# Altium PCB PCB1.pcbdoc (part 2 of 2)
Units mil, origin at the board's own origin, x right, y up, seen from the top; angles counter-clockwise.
Board outline 4100 x 4075 mil, 2 copper layers (Top Layer, Bottom Layer); 99 components, 67 nets, 330 pads, 1473 vias.
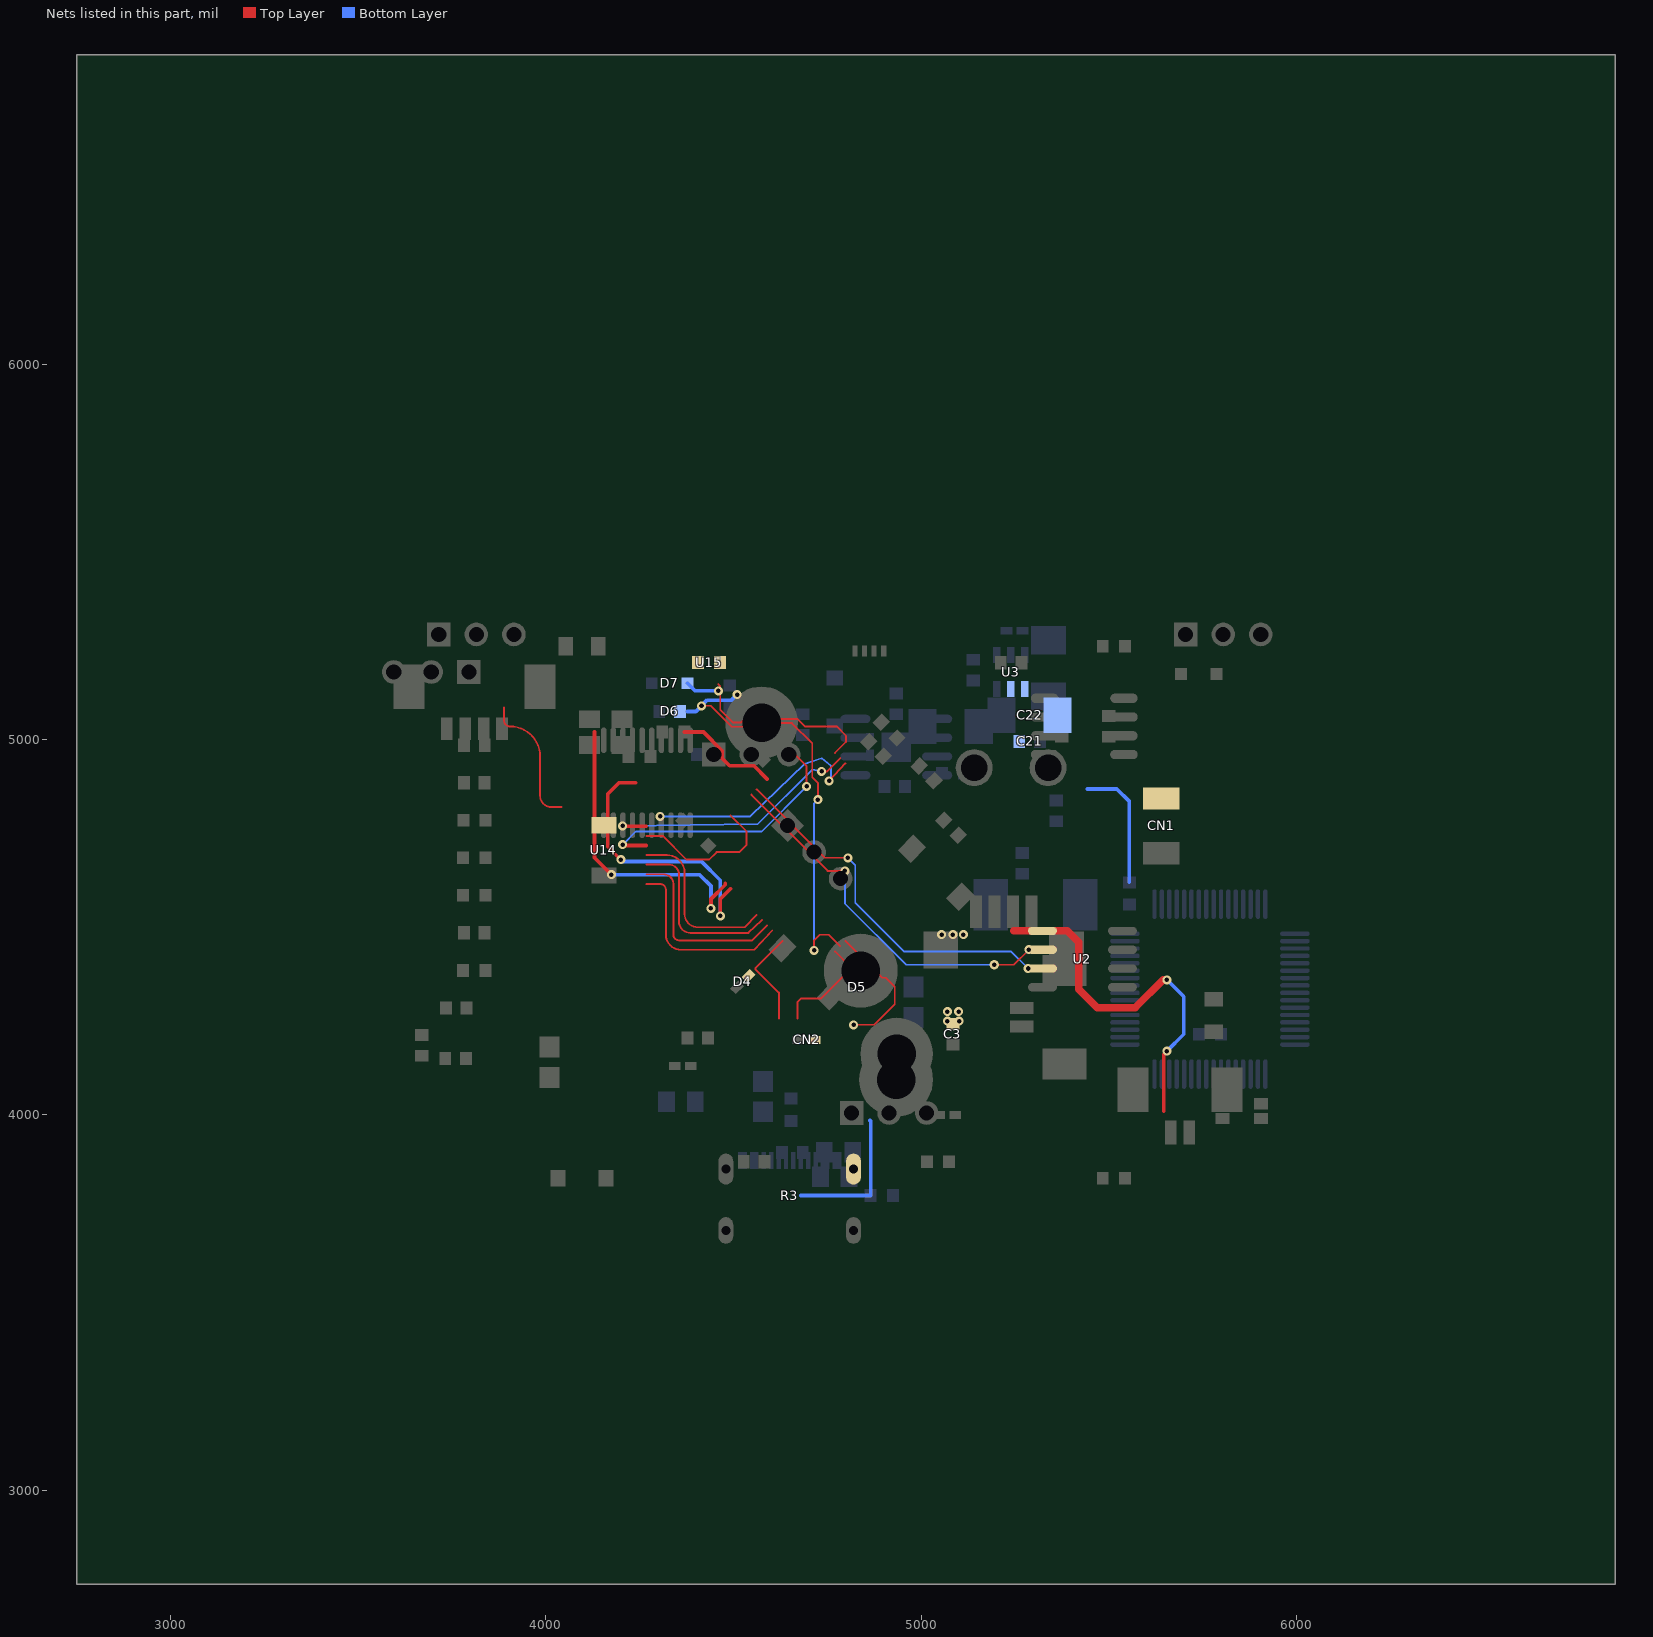
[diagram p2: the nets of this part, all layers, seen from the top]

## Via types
v1: diameter 24, hole 12, Top Layer to Bottom Layer, 1389 vias
v2: diameter 24.02, hole 12.01, Top Layer to Bottom Layer, 83 vias
v3: diameter 20.08, hole 12.01, Top Layer to Bottom Layer, 1 vias

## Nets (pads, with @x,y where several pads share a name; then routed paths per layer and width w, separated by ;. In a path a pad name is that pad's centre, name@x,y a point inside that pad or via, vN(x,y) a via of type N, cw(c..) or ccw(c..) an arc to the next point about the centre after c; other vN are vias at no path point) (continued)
SER.8:  | length 363.9
  Top Layer w5: 3888.74,5085 3888.74,5051.26 ccw(c3905,5051.26) 3905,5035 cw(c3905,4955) 3985,4955 3985,4850 ccw(c4014.84,4850) 4014.84,4820.16 4041.97,4820.16
SERVO_EN:  | length 361
  Top Layer w5: 4798.51,4463.37 4896.37,4365.51 4905.51,4365.51 4930,4341.02 4930,4295 4875,4240 v2(4820,4240)
SWD_CLK: CN2.2 D5.1 | length 284.6
  Top Layer w5: 4670.4,4256.1 4670.4,4300.4 4680,4310 4732.97,4310 4796.48,4373.52 4810,4387.03 4810,4396.21 4770.67,4435.53
SWD_IO: D4.1 | length 263.5
  Top Layer w5: 4621.2,4256.1 4621.2,4325.83 4558.52,4388.52 4558.52,4390.4 4631.49,4463.37
TIM1_CH1:  | length 464.8
  Top Layer w5: 4268.03,4692.21 4322.79,4692.21 cw(c4322.79,4645) 4370,4645 4370,4535 ccw(c4405,4535) 4405,4500 4530,4500 4561.89,4532.97
TIM1_CH2:  | length 478.7
  Top Layer w5: 4268.03,4666.61 4328.39,4666.61 cw(c4328.39,4640) 4355,4640 4355,4515 ccw(c4385,4515) 4385,4485 4540,4485 4575.81,4519.05
TIM1_CH3:  | length 496.8
  Top Layer w5: 4268.03,4641.02 4314.21,4641.02 cw(c4314.21,4615.23) 4340,4615.23 4340,4480 ccw(c4355,4480) 4355,4465 4549.59,4465 4589.73,4505.14
TIM1_CH4: U14.2 | length 509.2
  Top Layer w5: 4268.03,4615.43 ccw(c4268.46,4615.43) 4268.46,4615 4305,4615 cw(c4305,4600) 4320,4600 4320,4480 ccw(c4360,4480) 4360,4440 4555,4440 4603.65,4491.21
TIM2_CH1:  | length 624.8
  Top Layer w5: v2(4755,4890) 4798.51,4936.63
  Bottom Layer w5: v2(4305,4795) 4545,4795 4690,4935 4735,4950 4760,4930 v2@4760,4890
TIM2_CH2:  | length 718.2
  Top Layer w5: v2(4735,4915) 4750,4915 4784.59,4950.54
  Top Layer w10: v2(4205,4770) 4268.03,4768.98
  Bottom Layer w5: v2(4205,4770) 4565,4775 4710,4920 v2(4735,4915)
TIM2_CH3:  | length 405.1
  Top Layer w5: 4268.03,4743.39 4311.61,4743.39 4375,4680 4435,4680 4455,4700 4515,4700 4535,4720 4535,4755 4492.57,4797.43 4492.3,4797.43
TIM2_CH4:  | length 722.7
  Top Layer w5: 4659.33,4964.47 4695,4928.79 v2(4695,4875)
  Top Layer w10: v2(4205,4720) ccw(c4207.2,4720) 4207.2,4717.8 4268.03,4717.8
  Bottom Layer w5: v2(4205,4720) 4240,4755 4575,4755 v2(4695,4875)
TIM15_CH1:  | length 818.5
  Top Layer w10: 4130,5020 4130,4685 v2(4175,4640) ; v2(4440,4550) 4440,4575 4478.37,4613.37 4478.37,4616.49
  Bottom Layer w10: v2(4175,4640) 4410,4640 4440,4610 v2(4440,4550)
TIM15_CH2:  | length 743.6
  Top Layer w10: v2(4200,4680) 4165,4715 4165,4855 4195,4885 4240,4885 ; v2(4465,4530) 4465,4575.27 4492.3,4602.57
  Bottom Layer w10: v2(4200,4680) 4205,4675 4415,4675 4465,4625 v2(4465,4530)
TIM16_CH1:  | length 283.6
  Top Layer w10: 4369.66,5020 4420,5020 4470,4970 4470,4950 4490,4930 4554.59,4930 4589.73,4894.86
UART2_RX: D6.1 U15.1 | length 1173.3
  Top Layer w5: v2(4415,5090) 4439.44,5090 4495.44,5034 4524.56,5034 4534.56,5044 4656,5044 4710,4990 4710,4900 4725,4885 v2(4725,4840) ; v2(4715,4438.25) 4715,4465 4730,4480 4754.05,4480 4784.59,4449.46
  Bottom Layer w5: v2(4715,4438.25) 4715,4830 v2(4725,4840)
  Bottom Layer w10: 4377.4,5075 4400,5075 v2(4415,5090) 4430,5105 4495,5105 v2(4510,5120)
UART2_TX: D7.1 U15.2 | length 591
  Top Layer w5: 4459.6,5147.91 4465,5142.52 4465,5080 4500,5045 4520,5045 4530,5055 4670,5055 4690,5035 4775,5035 4800,5010 4800,4993.79 4770.67,4964.47
  Bottom Layer w10: D7.1@4377.4,5150 4397.4,5130 v2(4460,5130)
UART3_RX: U2.6 | length 992.7
  Top Layer w5: 4547.97,4853.11 4751.08,4650 v2@4795,4650 ; v2(5195,4400) 5247.55,4400 v2(5287.55,4440)
  Bottom Layer w5: v2(4797.31,4650) 4797.31,4562.69 4960,4400 v2(5195,4400)
UART3_TX: U2.7 | length 979.3
  Top Layer w5: 4561.89,4867.03 4743.92,4685 v2(4805,4685)
  Bottom Layer w5: v2(4805,4685) 4824.51,4665.49 4824.51,4565.49 4955,4435 5240,4435 v2(5285,4390)
USB_5V: U2.5 | length 987.4
  Top Layer w10: 5646.69,4010 5646.69,4161.69 v2(5655,4170)
  Top Layer w20: 5247.56,4490 5324.39,4490 5390,4490 5420,4460 5420,4335 5470,4285 5570,4285 5645,4360 v2(5655,4360)
  Bottom Layer w10: v2(5655,4170) 5700,4215 5700,4315 v2(5655,4360)
VCC: C3.1 C21.1 C22.1 CN1.2 U3.4 U3.5 | length 341
  Bottom Layer w10: 5443.15,4868.43 5521.57,4868.43 5555,4835 5555,4619.66
  other v2: 5070,4250 5101.64,4250 5070,4275 5100,4275 5055,4480 5085,4480 5112.44,4480
VREF1: R3.1 | length 386.9
  Bottom Layer w10: 4679.66,3785 4865.68,3785 4865.68,3982.72 ccw(c4863.7,3982.72) 4863.7,3984.7
"": 
pads on no net: C1.2 C2.2 C3.2 C4.2 C7.2 C8.2 C9.2 C10.2 C11.2 C12.2 C12.3 C12.4 C12.5 C12.6 C13.2 C13.3 C13.4 C13.5 C13.6 C13.7 C13.8 C13.9 C14.2 C14.3 C14.4 C15.2 C16.2 C18.1 C19.1 C20.2 C21.2 C22.2 C23.2 C24.2 C24.3 C25.2 C26.2 C27.2 C28.2 C28.3 C29.2 C79.2 CN1.1 CN2.1 D1.1 D2.2 D3.1 D4.2 D5.2 D6.2 D7.2 D8.2 D8.3 D9.2 D10.2 D11.2 H1.1 H1.2 H2.1 H2.2 H3.1 H3.2 H4.1 H4.2 L1.1 L2.2 LED1.2 LED2.2 LED2.3 LED2.4 LED3.1 R1.2 R2.2 R3.2 R3.3 R3.4 R3.A1B12 R3.A4B9 R3.A5 R3.A6 R3.A7 R3.A8 R3.B1A12 R3.B4A9 R3.B5 R3.B6 R3.B7 R3.B8 R4.2 R5.2 R6.2 R6.3 R6.4 R7.2 R8.2 R8.3 R8.4 R8.5 R8.6 R8.7 R8.8 R8.9 R8.10 R8.11 R8.12 R8.13 R8.14 R8.15 R8.16 R8.17 R8.18 R8.19 R8.20 R8.21 R8.22 R8.23 R8.24 R8.25 R8.26 R8.27 R8.28 R8.29 R8.30 R8.31 R8.32 R8.33 R8.34 R8.35 R8.36 R8.37 R8.38 R8.39 R8.40 R8.41 R8.42 R8.43 R8.44 R8.45 R8.46 R8.47 R8.48 R8.49 R8.50 R8.51 R8.52 R8.53 R8.54 R8.55 R8.56 R8.57 R8.58 R8.59 R8.60 R8.61 R8.62 R8.63 R8.64 R9.2 R10.2 R13.2 R13.3 R13.4 R13.5 R13.6 R13.7 R13.8 R14.2 R15.2 R15.3 R15.4 R15.5 R15.6 R15.7 R15.8 R15.9 R15.10 R15.11 R15.12 R15.13 R15.14 R15.15 R15.16 R15.17 R15.18 R15.19 R15.20 R16.2 R16.3 R16.4 R17.2 SW1.2 SW1.3 SW2.2 SW2.3 U2.1 U2.4 U3.6 U4.5 U5.2 U5.3 U6.2 U7.2 U8.2 U9.2 U10.2 U11.1 U12.1 U13.1 U14.1 U18.1 U19.1 U20.1 U21.1 U22.1 U23.1 U24.1 U25.1 U25.4 U25.5 U25.6 X1.1
copper on no net:
  other v1: 4914.33,4960.17 4953.73,4960.17 4914.33,4999.57 4953.73,4999.57

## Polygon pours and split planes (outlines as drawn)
GND on Top Layer (solid, remove dead copper): 3150,3350 6520,3350 6520,6155 3150,6155
GND on Bottom Layer (solid, remove dead copper, pour order 1): 3000,3000 6600,3000 6600,6575 3000,6575

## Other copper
Top Layer:
  region net VCC: 5045,4370 5125,4370 5125,4490 5045,4490
  region net SER.5V: 3775,3965 4210,3965 4210,4105 3775,4105
  region net SER.5V: 3776.02,4070 3845,4070 3845,5124.37 3776.02,5124.37
  pour cut-out net CAN_TX: 5162.5,4772.89 5167.5,4772.89 5173.75,4784.33 5156.25,4784.33
  pour cut-out net 5V: 5243.78,4859.85 5253.81,4845.7 5276.19,4845.7 5250.85,4866.92
  pour cut-out net CAN_RX: 5307.5,4775.5 5312.5,4775 5318.75,4780.76 5303.81,4791.3
  pour cut-out net CAN_H: 5217.5,4985.89 5223.75,4997.33 5206.25,4997.33 5212.5,4985.89
  pour cut-out net CAN_H: 5210.39,5083.9 5203.81,5058.7 5226.19,5058.7 5220.39,5083.5
  pour cut-out net CAN_L: 5267.5,4985.89 5273.75,4997.33 5256.25,4997.33 5262.5,4985.89
  pour cut-out net CAN_L: 5260,5083.71 5253.81,5058.7 5276.19,5058.7 5270,5083.71
  pour cut-out net $1N15560: 5321.46,5068.54 5303.81,5058.7 5326.19,5058.7 5328.54,5061.46
  pour cut-out net 5V: 4356.18,5191.18 4345.43,5179.41 4376.93,5179.41 4366.18,5191.18
  pour cut-out net UART2_TX: 4462.5,5108.92 4467.5,5108.92 4473.75,5116.42 4456.25,5116.42
  pour cut-out net 5V: 5113.82,3893.82 5123.82,3893.82 5134.57,3900.59 5103.07,3900.59
  pour cut-out net 5V: 5142.09,3941.93 5134.57,3963.58 5134.57,3900.59 5142.09,3922.24
  pour cut-out net I2C1_SCL: 5022.5,3971.08 5017.5,3971.08 5011.25,3963.58 5028.75,3963.58
  pour cut-out net I2C1_SDA: 4968.68,3971.08 4962.43,3963.58 4979.93,3963.58 4973.68,3971.08
  pour cut-out net 5V: 4659.57,3937.09 4644.57,3949.59 4644.57,3914.59 4659.57,3927.09
  pour cut-out net I2C2_SCL: 4525.4,3978.58 4514.65,3963.58 4546.14,3963.58 4535.4,3978.58
  pour cut-out net I2C2_SDA: 4476.18,3978.58 4465.43,3963.58 4496.93,3963.58 4486.18,3978.58
  pour cut-out net CAN_L: 4917.46,5152.91 4902.46,5165.41 4902.46,5130.41 4917.46,5142.91
  pour cut-out net CAN_H: 4832.5,5112.5 4842.5,5112.5 4853.25,5116.42 4821.75,5116.42
  pour cut-out net CAN_L: 5269.6,5194.41 5259.6,5194.41 5248.85,5179.41 5280.35,5179.41
  pour cut-out net CAN_L: 5260,5101.42 5270,5101.42 5280.35,5116.42 5248.85,5116.42
  pour cut-out net CAN_H: 5210.39,5101.42 5220.39,5101.42 5231.14,5116.42 5199.65,5116.42
  pour cut-out net CAN_H: 5196.01,5121.46 5208.65,5116.42 5199.65,5156.92 5189.04,5128.63
  pour cut-out net $1N20010: 4296.18,4905.55 4306.18,4905.55 4318.68,4920.55 4283.68,4920.55
  pour cut-out net 3V3: 4230.31,4940.31 4217.52,4950.08 4217.52,4920.55 4230.31,4930.31
  pour cut-out net $1N20360: 4296.18,5004.45 4283.68,4989.45 4318.68,4989.45 4306.18,5004.45
  pour cut-out net $1N20185: 4203.82,5004.45 4193.82,5004.45 4181.32,4989.45 4216.32,4989.45
  pour cut-out net 5V: 4220.77,4594.84 4220.77,4584.84 4240.9,4582.67 4240.9,4597.01
  pour cut-out net 5V: 4306.5,4594.84 4295.16,4597.01 4295.16,4582.67 4306.5,4584.84
  pour cut-out net TIM1_CH4: 4305,4612.5 4305,4617.5 4295.16,4622.6 4295.16,4608.26
  pour cut-out net TIM1_CH3: 4309.37,4643.52 4295.16,4648.19 4295.16,4633.85 4309.37,4638.52
  pour cut-out net TIM1_CH2: 4309.37,4669.11 4295.16,4673.78 4295.16,4659.44 4309.37,4664.11
  pour cut-out net TIM1_CH1: 4309.37,4694.71 4295.16,4699.38 4295.16,4685.04 4309.37,4689.71
  pour cut-out net TIM2_CH4: 4220.77,4712.8 4240.9,4710.63 4240.9,4724.97 4220.77,4722.8
  pour cut-out net TIM2_CH3: 4309.37,4745.89 4295.16,4750.56 4295.16,4736.22 4309.37,4740.89
  pour cut-out net TIM2_CH2: 4221.33,4774.74 4220.31,4764.75 4240.9,4761.81 4240.9,4776.15
  pour cut-out net 5V: 4089.23,4594.84 4069.1,4597.01 4069.1,4582.67 4089.23,4584.84
  pour cut-out net SER.1: 4000.33,4642.5 4001.1,4637.5 4014.84,4633.85 4014.84,4648.19
  pour cut-out net SER.2: 4000.23,4667.5 4001.47,4662.5 4014.84,4659.44 4014.24,4673.75
  pour cut-out net SER.3: 4000.63,4694.71 4000.63,4689.71 4014.84,4685.04 4014.84,4699.38
  pour cut-out net SER.4: 4001.94,4722.5 4000.18,4717.5 4011.94,4711.25 4014.84,4724.97
  pour cut-out net SER.5: 4000.63,4745.89 4000.63,4740.89 4014.84,4736.22 4014.84,4750.56
  pour cut-out net SER.6: 4001.1,4772.5 4000.33,4767.5 4014.84,4761.81 4014.84,4776.15
  pour cut-out net SER.7: 4000.63,4797.07 4000.63,4792.07 4014.84,4787.4 4014.84,4801.74
  pour cut-out net SER.8: 4001.5,4826.14 4000.82,4820.86 4014.84,4812.99 4014.84,4827.33
  pour cut-out net OSC_IN: 5091.15,4875.32 5094.68,4878.85 5093.8,4888.58 5081.42,4876.2
  pour cut-out net OSC_OUT: 4955.02,4877.46 4965.02,4877.46 4977.52,4894.79 4942.52,4900.36
  pour cut-out net SERVO_EN: 4842.38,4423.04 4838.84,4419.5 4841.85,4411.9 4852.1,4422.16
  pour cut-out net SERVO_EN: 4878.04,4387.38 4877.16,4397.1 4841.85,4411.9 4874.5,4383.84
  pour cut-out net $1N9916: 3675,4245.54 3665,4245.54 3652.99,4230.54 3687.01,4230.54
  pour cut-out net $1N9916: 3690,4280 3698.7,4267.5 3698.7,4302.5 3690,4290
  pour cut-out net CAN_H: 5432.5,4981.96 5437.5,4981.96 5443.75,4989.46 5426.25,4989.46
  pour cut-out net $1N15560: 5467.01,5069.66 5452.01,5080.54 5452.01,5048.78 5467.01,5059.66
  pour cut-out net $1N15560: 5402.99,5070 5402.99,5060 5417.99,5048.78 5417.99,5080.54
  pour cut-out net CAN_L: 5377.5,4985 5383.75,4989.8 5366.25,4989.8 5372.5,4985
  pour cut-out net $1N15560: 5407.01,5070 5392.01,5080.88 5392.01,5049.12 5407.01,5060
  pour cut-out net $1N15560: 5342.99,5070 5342.99,5060 5357.99,5049.12 5357.99,5080.88
  pour cut-out net $1N15560: 5467.28,5069.66 5467.28,5059.66 5482.28,5047.16 5482.28,5078.31
  pour cut-out net $1N19092: 5724.65,4338.9 5709.65,4339.8 5709.65,4328 5724.65,4328.9
  pour cut-out net DP: 5649.35,4300 5649.35,4290 5664.35,4288.6 5664.35,4300.4
  pour cut-out net DN: 5649.35,4269.8 5664.35,4268.9 5664.35,4280.7 5649.35,4279.8
  pour cut-out net DN: 5655,4240 5655,4230 5664.35,4229.6 5664.35,4241.4
  pour cut-out net $1N19093: 5724.65,4220.8 5709.65,4221.7 5709.65,4209.9 5724.65,4210.8
  pour cut-out net $1N19102: 5330,4312.6 5342.5,4327.6 5307.5,4327.6 5320,4312.6
  pour cut-out net USB_5V: 5262.74,4500 5262.74,4480 5300.08,4477.6 5300.08,4502.4
  pour cut-out net USB_5V: 5386.04,4500 5348.7,4502.4 5348.7,4477.6 5386.04,4480
  pour cut-out net USB_5V: 5293.31,4500 5263.31,4507.72 5263.31,4472.28 5293.31,4480
  pour cut-out net $1N19102: 5330,4318.31 5320,4318.31 5307.5,4303.31 5342.5,4303.31
  pour cut-out net USB_5V: 5641.69,4049.6 5629.19,4034.6 5664.19,4034.6 5651.69,4049.6
  pour cut-out net $1N19108: 5768,4015 5753,4027.5 5753,3992.5 5768,4005
  pour cut-out net $1N19108: 5794.12,4015 5794.12,4005 5809.12,3992.99 5809.12,4027.01
  pour cut-out net TIM15_CH2: 4209.12,4890 4209.12,4880 4224.12,4867.99 4224.12,4902.01
  pour cut-out net $1N20010: 4296.18,4917.01 4283.68,4902.01 4315.2,4902.01 4306.18,4917.01
  pour cut-out net TIM15_CH1: 4125,4987.99 4135,4987.99 4145.88,5002.99 4114.12,5002.99
  pour cut-out net $1N20185: 4203.82,4987.99 4205.2,5002.99 4181.32,5002.99 4193.82,4987.99
  pour cut-out net TIM16_CH1: 4400.54,5015 4400.54,5025 4385.54,5037.01 4385.54,5002.99
  pour cut-out net $1N20360: 4296.18,4987.99 4306.18,4987.99 4318.68,5002.99 4294.46,5002.99
  pour cut-out net RST: 5691.39,5154.92 5695.52,5151.98 5709.66,5157.28 5696.69,5169.07
  pour cut-out net RST: 5709.4,5207.72 5696.9,5192.72 5728.19,5192.72 5719.4,5207.72
  pour cut-out net KEY: 3720,5212.72 3707.5,5197.72 3738.31,5197.72 3730,5212.72
  pour cut-out net CAN_TX: 4984.88,4586.77 4979.47,4597 4971.11,4588.65 4981.35,4583.23
  pour cut-out net CAN_RX: 4972.04,4571.77 4965.54,4583.08 4957.19,4574.73 4968.5,4568.23
  pour cut-out net I2C1_SDA: 4940.85,4540.21 4944.38,4543.75 4937.7,4555.24 4929.35,4546.89
  pour cut-out net I2C1_SCL: 4930.47,4529.83 4923.79,4541.33 4915.44,4532.97 4926.93,4526.3
  pour cut-out net SERVO_EN: 4833.03,4432.39 4826.35,4443.89 4818,4435.53 4829.49,4428.86
  pour cut-out net UART2_RX: 4755.82,4481.77 4752.28,4478.23 4756.75,4468.95 4765.11,4477.3
  pour cut-out net SWD_CLK: 4805.19,4404.55 4798.51,4416.05 4790.16,4407.7 4801.65,4401.02
  pour cut-out net 3V3: 4660,4420 4687.17,4455.02 4637.5,4422.06 4650,4420
  pour cut-out net SWD_IO: 4600.51,4428.86 4612,4435.53 4603.65,4443.89 4596.97,4432.39
  pour cut-out net TIM1_CH4: 4573.91,4456.28 4584.16,4463.37 4575.81,4471.73 4569.73,4459.13
  pour cut-out net TIM1_CH3: 4555.21,4474.15 4558.75,4470.62 4570.24,4477.3 4561.89,4485.65
  pour cut-out net TIM1_CH2: 4540.88,4489.29 4543.75,4485.11 4556.33,4491.21 4547.97,4499.56
  pour cut-out net TIM1_CH1: 4528.2,4501.74 4531.8,4498.26 4542.4,4505.14 4534.05,4513.49
  pour cut-out net TIM15_CH2: 4461.46,4578.81 4468.54,4571.74 4471.1,4573.54 4463.27,4581.37
  pour cut-out net I2C2_SCL: 4431.07,4597.53 4444.61,4602.24 4436.62,4610.92 4429.95,4603.49
  pour cut-out net 3V3: 4432.28,4744.36 4439.36,4737.28 4458.8,4739.05 4434.05,4763.8
  pour cut-out net I2C2_SDA: 4512.89,4752.53 4506.21,4764.02 4497.86,4755.67 4509.36,4748.99
  pour cut-out net TIM2_CH3: 4523.47,4762.99 4526.88,4766.65 4520.14,4777.95 4511.78,4769.59
  pour cut-out net KEY: 4499.53,4870.17 4506.21,4858.67 4514.56,4867.03 4503.07,4873.7
  pour cut-out net UART3_RX: 4582.49,4822.13 4575.81,4833.62 4567.46,4825.27 4578.96,4818.59
  pour cut-out net UART3_TX: 4596.41,4836.04 4589.73,4847.54 4581.38,4839.19 4592.87,4832.51
  pour cut-out net TIM16_CH1: 4551.06,4926.46 4561.89,4914.35 4570.24,4922.7 4558.13,4933.54
  pour cut-out net 3V3: 4606.83,4968.36 4599.76,4961.29 4603.65,4956.11 4612,4964.47
  pour cut-out net TIM2_CH4: 4690.31,4929.95 4693.85,4933.48 4687.17,4944.98 4678.82,4936.63
  pour cut-out net UART2_TX: 4798.23,4995.56 4790.16,4992.3 4798.51,4983.95 4801.77,4992.03
  pour cut-out net TIM2_CH2: 4750.37,4918.96 4754.25,4915.78 4765.11,4922.7 4756.75,4931.05
  pour cut-out net TIM2_CH1: 4764.82,4904.19 4769.24,4901.59 4779.02,4908.79 4770.67,4917.14
  pour cut-out net 3V3: 4783.54,4886.74 4792.95,4894.86 4784.59,4903.22 4776.46,4893.81
  pour cut-out net 3V3: 4845.39,4962.73 4831.92,4950.54 4840.27,4942.19 4852.46,4955.66
  pour cut-out net RST: 4923.23,4870.01 4915.44,4867.03 4923.79,4858.67 4926.77,4866.47
  pour cut-out net OSC_OUT: 4942.82,4865.3 4929.35,4853.11 4937.7,4844.76 4949.89,4858.23
  pour cut-out net OSC_IN: 4950.67,4841.77 4943.27,4839.19 4951.63,4830.84 4954.21,4838.23
  pour cut-out net 3V3: 4939.44,4722.71 4946.51,4715.64 4959.98,4727.83 4951.63,4736.18
  pour cut-out net 3V3: 4990.71,4737.35 4997.78,4744.42 4996.02,4763.87 4971.27,4739.12
  pour cut-out net 3V3: 5013.54,4641.81 5028.31,4641.66 5006.31,4663.66 5006.46,4648.88
  pour cut-out net 3V3: 5019.83,4692.17 5007.33,4664.67 5043.34,4656.69 5029.83,4685.21
  pour cut-out net 3V3: 4654.51,4413.42 4661.14,4398.83 4676.17,4413.86 4661.58,4420.49
  pour cut-out net 3V3: 4403.88,4716.46 4418.66,4716.31 4396.66,4738.31 4396.81,4723.54
  pour cut-out net 3V3: 4437.09,4749.16 4417.64,4747.39 4433.69,4731.34 4444.16,4742.09
  pour cut-out net 3V3: 4529.97,4965 4539.97,4955 4563.66,4946.31 4550.85,4977.5
  pour cut-out net 3V3: 4585.21,4969.83 4556.69,4983.34 4564.67,4947.33 4592.17,4959.83
  pour cut-out net 3V3: 4846.46,4978.88 4853.54,4971.81 4868.31,4971.66 4846.31,4993.66
  pour cut-out net 3V3: 4879.41,5011.83 4861.34,5008.69 4883.34,4986.69 4886.48,5004.76
  pour cut-out net SWD_IO: 4623.7,4293.15 4618.7,4293.15 4612.45,4285.65 4629.95,4285.65
  pour cut-out net SWD_CLK: 4672.9,4293.15 4667.9,4293.15 4661.65,4285.65 4679.15,4285.65
  pour cut-out net 3V3: 4773.8,4211.55 4784.55,4226.55 4753.05,4226.55 4763.8,4211.55
  pour cut-out net SWD_CLK: 4781.81,4355.31 4791.53,4356.19 4779.16,4368.57 4778.28,4358.84
  pour cut-out net SWD_CLK: 4811.77,4385.27 4808.23,4388.8 4801.43,4390.84 4813.81,4378.47
  pour cut-out net SWD_IO: 4576.72,4373.84 4575.84,4383.57 4563.47,4371.19 4573.19,4370.31
  pour cut-out net SWD_IO: 4575.78,4404.13 4572.25,4407.67 4562.53,4406.78 4574.9,4394.41
  pour cut-out net SER.1: 3885.88,4413.38 3879.63,4412.56 3897.13,4412.56 3890.88,4413.38
  pour cut-out net SER.2: 3885.88,4518.38 3879.63,4512.56 3897.13,4512.56 3890.88,4518.38
  pour cut-out net SER.3: 3885.88,4613.38 3879.63,4612.56 3897.13,4612.56 3890.88,4613.38
  pour cut-out net SER.4: 3897.55,4717.16 3890.49,4718.82 3880.06,4712.56 3894.34,4712.56
  pour cut-out net SER.5: 3892.5,4755 3898.75,4757.44 3881.25,4757.44 3887.5,4755
  pour cut-out net SER.6: 3890.88,4851.62 3897.13,4857.44 3879.63,4857.44 3885.88,4851.62
  pour cut-out net SER.7: 3892.5,4949.94 3898.75,4957.44 3881.25,4957.44 3887.5,4949.94
  pour cut-out net SER.8: 3891.24,5051.26 3897.49,5057.44 3879.99,5057.44 3886.24,5051.26
  pour cut-out net RST: 5709.4,5235.45 5719.4,5235.45 5731.9,5250.45 5696.9,5250.45
  pour cut-out net KEY: 3720,5235.45 3730,5235.45 3742.5,5250.45 3707.5,5250.45
  pour cut-out net I2C1_SDA: 4968.68,3981.75 4973.68,3981.75 4978.15,3989.25 4962.43,3989.25
  pour cut-out net I2C1_SDA: 4968.68,4028.25 4962.43,4020.75 4978.15,3989.25 4973.68,4028.25
  pour cut-out net I2C1_SCL: 5022.5,3976.75 5028.75,3984.25 5011.25,3984.25 5017.5,3976.75
  pour cut-out net I2C1_SCL: 5001.55,4016.99 5001.55,4009.92 5006.85,3995.78 5011.62,4015.75
  pour cut-out net I2C2_SDA: 4410,4099.25 4420,4099.25 4428.15,4114.25 4397.5,4114.25
  pour cut-out net I2C2_SDA: 4410,4160.75 4397.5,4145.75 4428.15,4114.25 4420,4160.75
  pour cut-out net I2C2_SCL: 4440,4174.25 4450,4174.25 4462.5,4189.25 4436.65,4189.25
  pour cut-out net I2C2_SCL: 4440,4235.75 4436.65,4189.25 4462.5,4220.75 4450,4235.75
  pour cut-out net OSC_IN: 5033.24,4786.99 5030.46,4781.99 5044.21,4775.74 5046.99,4793.24
  pour cut-out net OSC_IN: 5076.58,4804.09 5066.85,4803.2 5079.23,4790.83 5080.11,4800.55
  pour cut-out net USB_5V: 5643,4170.5 5641.69,4154.48 5651.69,4144.9 5656.01,4158.03
  pour cut-out net $1N19092: 5731.27,4343.24 5719.14,4338.9 5720.06,4328.9 5732.92,4325.3
  pour cut-out net $1N19093: 5732.68,4224.52 5719.93,4220.8 5719.26,4210.8 5731.48,4206.54
  pour cut-out net SERVO_EN: 4827.94,4230.99 4840.41,4237.5 4840.41,4242.5 4827.94,4249.01
  pour cut-out net $1N4618: 5210.99,4712.06 5215,4699.59 5225,4699.59 5229.01,4712.06
  pour cut-out net $1N4618: 5362.06,4574.01 5349.59,4570 5349.59,4560 5362.06,4555.99
  pour cut-out net TIM2_CH4: 4211.16,4709.69 4224.42,4712.8 4226.29,4722.8 4214.46,4727.4
  pour cut-out net TIM2_CH4: 4704.01,4882.94 4697.5,4895.41 4692.5,4895.41 4685.99,4882.94
  pour cut-out net TIM2_CH2: 4212.8,4760.87 4225.33,4764.67 4225.49,4774.67 4213.09,4778.88
  pour cut-out net TIM2_CH2: 4742.94,4905.99 4750,4912.5 4750,4917.5 4742.94,4924.01
  pour cut-out net TIM2_CH1: 4767,4889.66 4770.75,4903.22 4767.1,4906.63 4753.83,4901.95
  pour cut-out net 5V: 4152.6,4580.83 4165.07,4584.84 4165.07,4594.84 4152.6,4598.85
  pour cut-out net 5V: 4136.72,4598.85 4124.25,4594.84 4124.25,4584.84 4136.72,4580.83
  pour cut-out net 3V3: 4507.94,4950.99 4520.41,4955 4520.41,4965 4507.94,4969.01
  pour cut-out net 3V3: 4526.98,5069.25 4532.97,5080.9 4525.9,5087.97 4514.25,5081.98
  pour cut-out net I2C2_SDA: 4509.24,4717.34 4519.7,4731.16 4518.23,4736.77 4506.45,4735.13
  pour cut-out net 3V3: 4675.75,4411.98 4664.1,4417.97 4657.03,4410.9 4663.02,4399.25
  pour cut-out net 3V3: 4565.99,4287.06 4570,4274.59 4580,4274.59 4584.01,4287.06
  pour cut-out net I2C2_SCL: 4426.98,4584.25 4431.2,4597.67 4427.67,4601.2 4414.25,4596.98
  pour cut-out net I2C2_SCL: 4435.99,4247.06 4440,4234.59 4450,4234.59 4454.01,4247.06
  pour cut-out net I2C2_SDA: 4448.02,4385.75 4442.03,4374.1 4449.1,4367.03 4460.75,4373.02
  pour cut-out net TIM15_CH2: 4474.01,4537.94 4470,4550.41 4460,4550.41 4455.99,4537.94
  pour cut-out net TIM15_CH1: 4449.01,4557.94 4445,4570.41 4435,4570.41 4430.99,4557.94
  pour cut-out net TIM15_CH1: 4175.75,4651.98 4164.1,4657.97 4157.03,4650.9 4163.02,4639.25
  pour cut-out net TIM15_CH2: 4200.75,4691.98 4189.1,4697.97 4182.03,4690.9 4188.02,4679.25
  pour cut-out net 5V: 4737.19,5101.67 4725.61,5106.46 4720.72,5097.21 4728.77,5085.75
  pour cut-out net UART2_RX: 4724.01,4446.19 4717.5,4458.66 4712.5,4458.66 4705.99,4446.19
  pour cut-out net UART2_RX: 4734.01,4847.94 4727.5,4860.41 4722.5,4860.41 4715.99,4847.94
  pour cut-out net UART2_RX: 4422.94,5080.99 4435.41,5087.5 4435.41,5092.5 4422.94,5099.01
  pour cut-out net I2C1_SCL: 4956.5,4498.47 4952.5,4506.76 4947.5,4506.76 4940.12,4505.97
  pour cut-out net I2C1_SCL: 4975.99,4532.06 4982.5,4519.59 4987.5,4519.59 4994.01,4532.06
  pour cut-out net UART2_TX: 4471.5,5133.47 4455.12,5140.97 4462.5,5080 4467.5,5080
  pour cut-out net UART2_TX: 4455.12,5119.03 4462.5,5108.69 4467.5,5110.98 4471.5,5126.53
  pour cut-out net 5V: 4972.94,5045.99 4985.41,5050 4985.41,5060 4972.94,5064.01
  pour cut-out net KEY: 4488.01,4873.16 4501.59,4868.11 4505.49,4871.28 4502,4884.5
  pour cut-out net KEY: 3734.01,5187.94 3730,5200.41 3720,5200.41 3715.99,5187.94
  pour cut-out net RST: 5062.06,5099.01 5049.59,5092.5 5049.59,5087.5 5062.06,5080.99
  pour cut-out net RST: 5182.94,5250.99 5195.41,5257.5 5195.41,5262.5 5182.94,5269.01
  pour cut-out net UART3_RX: 4789.36,4659.01 4776.89,4652.5 4776.89,4647.5 4789.36,4640.99
  pour cut-out net UART3_TX: 4797.06,4694.01 4784.59,4687.5 4784.59,4682.5 4797.06,4675.99
  pour cut-out net UART3_RX: 5202.94,4390.99 5215.41,4397.5 5215.41,4402.5 5202.94,4409.01
  pour cut-out net UART3_RX: 5275.56,4440.75 5271.35,4427.33 5274.88,4423.8 5288.3,4428.02
  pour cut-out net DP: 5637.94,4285.99 5650.41,4290 5650.41,4300 5637.94,4304.01
  pour cut-out net DN: 5617.94,4205.99 5630.41,4210 5630.41,4220 5617.94,4224.01
  pour cut-out net DN: 5612.94,4260.99 5625.41,4265 5625.41,4275 5612.94,4279.01
  pour cut-out net DP: 5577.94,4235.99 5590.41,4240 5590.41,4250 5577.94,4254.01
  pour cut-out net 3V3: 4228.02,4945.75 4226.78,4938.85 4233.85,4931.78 4240.75,4933.02
  pour cut-out net KEY: 4473.56,4892.94 4467.06,4905.41 4462.06,4905.41 4455.55,4892.94
  pour cut-out net OSC_OUT: 4945.57,4874.31 4940.2,4862.68 4948.12,4856.46 4959.74,4863.19
  pour cut-out net OSC_OUT: 4968,4880.93 4965.02,4894.3 4955.02,4896.39 4950.37,4884.62
Bottom Layer:
  region net BAT-: 5275,4620 5485,4620 5485,4800 5275,4800
  region net 5V: 4720,4980 5035,4980 5035,5065.01 4720,5065.01
  region net 5V: 4650,5000 4725,5000 4725,5037.33 4650,5037.33
  region net 3V3: 4435,4940.76 4541.54,4940.76 4541.54,5085.01 4435,5085.01
  region net $1N3621: 5120,4885 5185,4885 5185,5000 5120,5000
  region net VCC: 5225,5105 5225,4951.62 ccw(c5358.12,4951.62) 5358.12,4818.5 5448.5,4818.5 ccw(c5448.5,4875) 5505,4875 ccw(c5455,4875) 5455,4925 5310,4925 cw(c5310,4955) 5280,4955 5280,5090 cw(c5295,5090) 5295,5105 ccw(c5295,5110.06) 5300.06,5110.06 5300.06,5144.43 ccw(c5299.63,5144.43) 5299.63,5144.87 5299.63,5150.37 ccw(c5280,5150.37) 5280,5170 5225,5170
  region net $1N3621: 5151.83,4983.88 5178.88,4983.88 ccw(c5178.88,4990) 5185,4990 5185,5085 cw(c5195,5085) 5195,5095 5205,5095 ccw(c5205,5105) 5215,5105 5215,5147.52 cw(c5215.39,5147.52) 5215.39,5147.91 ccw(c5203.31,5147.91) 5203.31,5160 5180,5160 cw(c5180,5173.02) 5166.98,5173.02 5166.98,5173.83 ccw(c5158.12,5173.83) 5158.12,5182.69 5125.08,5182.69 ccw(c5125.08,5177.61) 5120,5177.61 5120,4986.98 ccw(c5123.29,4986.98) 5123.29,4983.7 5151.64,4983.7 ccw(c5151.64,4983.88)
  region net 3V3: 4610.31,5000.32 4444.68,5000.32 cw(c4444.68,5010) 4435,5010 4435,5068.83 cw(c4448.65,5068.83) 4448.65,5082.48 4537.52,5082.48 cw(c4537.52,5075) 4545,5075 4545,5055 ccw(c4560,5055) 4560,5040 4585,5040 cw(c4585,5035) 4590,5035 4590,5030.38 ccw(c4602.44,5030.38) 4602.44,5017.95 cw(c4602.44,5010.07) 4610.31,5010.07
  region net VCC: 5225,4945 cw(c5135.93,4929.74) 5186.73,4855 5155,4855 ccw(c5155,4740) 5040,4740 5040,4481.36 ccw(c5056.36,4481.36) 5056.36,4465 5110,4465 ccw(c5110,4490) 5135,4490 5135,4745 cw(c5190,4745) 5190,4800 5225,4800 ccw(c5207.67,4860.08) 5270,4865 5273.07,4866.81 ccw(c5171.5,4858.23)
  region net VCC: 5356.16,4818.5 5268.5,4818.5 ccw(c5268.5,4805) 5255,4805 cw(c5250,4805) 5250,4800 5167.95,4800 ccw(c5167.95,4797.05) 5165,4797.05 cw(c5222.95,4797.05) 5222.95,4855 5230,4855 cw(c5250,4855) 5250,4875 5305,4875 cw(c5305,4823.84) 5356.16,4823.84
  region net VCC: 4950.54,4234.46 cw(c4950.54,4255) 4930,4255 ccw(c4915,4255) 4915,4270 4800,4270 ccw(c4800,4250) 4780,4250 4780,4170 cw(c4770,4170) 4770,4160 4755,4160 cw(c4755,4170) 4745,4170 4745,4260 cw(c4790,4260) 4790,4305 4925,4305 cw(c4925.8,4265.69) 4945,4300 ccw(c4960.76,4320.55) 4965,4295 5107,4293 cw(c5107,4285) 5115,4285 5115,4245 cw(c5105,4245) 5105,4235 cw(c5104.46,4235) 5104.46,4234.46
  region net $1N9919: 4700.77,3944.23 cw(c4700.77,3955) 4690,3955 ccw(c4680,3955) 4680,3965 4530,3965 cw(c4530,4015.5) 4479.5,4015.5 4479.5,4035 4505,4035 cw(c4505,4015) 4525,4015 4606,4015 cw(c4606,4008.2) 4612.8,4008.2 ccw(c4618.33,4008.2) 4618.33,4002.67 4685.91,4002.67 ccw(c4685.91,4014.01) 4697.25,4014.01 cw(c4713.25,4014.01) 4713.25,4030 4715,4030 cw(c4715,4015) 4730,4015 4730,3955 cw(c4720,3955) 4720,3945 cw(c4719.23,3945) 4719.23,3944.23
  pour cut-out net FB: 5298.88,5229.07 5286.88,5239.07 5286.88,5211.07 5298.88,5221.07
  pour cut-out net FB: 5271.43,5261.17 5265.98,5246.17 5286.88,5246.17 5281.43,5261.17
  pour cut-out net $1N5688: 5188.99,5217.43 5188.99,5207.43 5210.51,5203.97 5191.18,5219.96
  pour cut-out net VCC: 5475.7,4831.52 5521.57,4863.43 5521.57,4873.43 5475.7,4905.33
  pour cut-out net 5V: 5002.23,5096.07 4992.23,5084.07 5020.23,5084.07 5010.23,5096.07
  pour cut-out net FB: 5310.02,5229.07 5310.02,5221.07 5322.02,5211.07 5322.02,5235.4
  pour cut-out net 5V: 5191.49,5294 5191.49,5286 5203.49,5276 5203.49,5304
  pour cut-out net FB: 5271.43,5257.86 5281.43,5257.86 5293.93,5272.86 5262.81,5272.86
  pour cut-out net VCC: 5550,4650.54 5537.99,4635.54 5572.01,4635.54 5560,4650.54
  pour cut-out net $1N4618: 5522.99,4565 5522.99,4555 5537.99,4544.46 5537.99,4576.22
  pour cut-out net $1N4618: 5408.55,4565 5393.55,4577.5 5393.55,4542.5 5408.55,4555
  pour cut-out net $1N5688: 5171.74,5217.43 5156.74,5228.17 5156.74,5196.68 5171.74,5207.43
  pour cut-out net $1N9925: 4687.7,4197.7 4702.4,4185.2 4702.4,4220.2 4687.7,4207.7
  pour cut-out net $1N9926: 4818.7,3930.77 4825,3955.9 4802.4,3955.9 4808.7,3930.77
  pour cut-out net VREF1: 4860.68,3930.01 4870.68,3932.01 4875,3955.9 4852.4,3955.9
  pour cut-out net $1N9922: 4902.28,4185 4917.28,4174.25 4917.28,4205.75 4902.28,4195
  pour cut-out net $1N9926: 4792.56,3867.72 4781.81,3852.72 4813.31,3852.72 4802.56,3867.72
  pour cut-out net $1N9912: 4715.75,3905 4700.75,3917.5 4700.75,3882.5 4715.75,3895
  pour cut-out net $1N9912: 4719.46,3905 4719.46,3895 4734.46,3882.99 4734.46,3917.01
  pour cut-out net $1N9926: 4818.7,3932.01 4808.7,3932.01 4796.2,3917.01 4825.54,3917.01
  pour cut-out net SER.5V: 4250,3951.1 4260,3951.1 4272.5,3966.1 4237.5,3966.1
  pour cut-out net $1N9925: 4660,4072.01 4650,4072.01 4637.5,4057.01 4671.42,4057.01
  pour cut-out net SER.5V: 4589.46,3780 4604.46,3767.99 4604.46,3802.01 4589.46,3790
  pour cut-out net VREF1: 4710.54,3790 4695.54,3802.01 4695.54,3767.99 4710.54,3780
  pour cut-out net VREF1: 4834.8,3790 4834.8,3780 4849.8,3767.99 4849.8,3802.01
  pour cut-out net VREF1: 4860.68,3817.01 4849.8,3802.01 4881.56,3802.01 4870.68,3817.01
  pour cut-out net UART2_RX: 4400,5080 4393.15,5090.75 4393.15,5059.25 4400,5070
  pour cut-out net UART2_TX: 4393.86,5126.46 4400.94,5133.54 4393.15,5159 4368.4,5134.25
  pour cut-out net USB_5V: 5654.25,4348.02 5665.9,4342.03 5672.97,4349.1 5666.98,4360.75
  pour cut-out net USB_5V: 5666.98,4169.25 5672.97,4180.9 5665.9,4187.97 5654.25,4181.98
  pour cut-out net $1N4618: 5373.47,4553.5 5387.87,4555 5392.45,4565 5380.97,4569.88
  pour cut-out net TIM2_CH4: 4216.98,4719.25 4221.2,4732.67 4217.67,4736.2 4204.25,4731.98
  pour cut-out net TIM2_CH4: 4683.02,4875.75 4678.8,4862.33 4682.33,4858.8 4695.75,4863.02
  pour cut-out net TIM2_CH2: 4213.07,4761.11 4225.45,4767.78 4225.38,4772.78 4212.82,4779.12
  pour cut-out net TIM2_CH2: 4728.98,4925.39 4715.47,4921.45 4714.49,4916.55 4725.45,4907.73
  pour cut-out net TIM2_CH1: 4312.94,4785.99 4325.41,4792.5 4325.41,4797.5 4312.94,4804.01
  pour cut-out net TIM2_CH1: 4766.5,4893.47 4762.5,4909.02 4757.5,4911.31 4750.12,4900.97
  pour cut-out net 5V: 4153.67,4597.78 4149.66,4610.25 4139.66,4610.25 4135.66,4597.78
  pour cut-out net 3V3: 4434.87,4943.55 4429.67,4931.74 4441.9,4929.82 4452.66,4940.76
  pour cut-out net I2C2_SDA: 4490.99,4717.06 4495,4704.59 4505,4704.59 4509.01,4717.06
  pour cut-out net 3V3: 4663.33,4397.19 4658.54,4385.61 4667.79,4380.72 4679.25,4388.77
  pour cut-out net 3V3: 4586.98,4294.25 4592.97,4305.9 4585.9,4312.97 4574.25,4306.98
  pour cut-out net I2C2_SCL: 4405.99,4577.06 4410,4564.59 4420,4564.59 4424.01,4577.06
  pour cut-out net I2C2_SCL: 4445.75,4266.98 4434.1,4272.97 4427.03,4265.9 4433.02,4254.25
  pour cut-out net I2C2_SDA: 4471.98,4384.25 4477.97,4395.9 4470.9,4402.97 4459.25,4396.98
  pour cut-out net TIM15_CH2: 4474.01,4537.94 4470,4550.41 4460,4550.41 4455.99,4537.94
  pour cut-out net TIM15_CH1: 4449.01,4557.94 4445,4570.41 4435,4570.41 4430.99,4557.94
  pour cut-out net TIM15_CH1: 4182.94,4630.99 4195.41,4635 4195.41,4645 4182.94,4649.01
  pour cut-out net TIM15_CH2: 4203.47,4668.5 4217.87,4670 4222.45,4680 4210.97,4684.88
  pour cut-out net 5V: 4739.25,5078.02 4750.9,5072.03 4757.97,5079.1 4751.98,5090.75
  pour cut-out net UART2_RX: 4498.02,5120.75 4492.03,5109.1 4499.1,5102.03 4510.75,5108.02
  pour cut-out net UART2_RX: 4724.01,4446.19 4717.5,4458.66 4712.5,4458.66 4705.99,4446.19
  pour cut-out net UART2_RX: 4713.02,4840.75 4713.23,4831.77 4716.77,4828.23 4725.75,4828.02
  pour cut-out net UART2_RX: 4403.02,5090.75 4397.03,5079.1 4404.1,5072.03 4415.75,5078.02
  pour cut-out net UART2_RX: 4426.98,5089.25 4432.97,5100.9 4425.9,5107.97 4414.25,5101.98
  pour cut-out net I2C1_SCL: 4956.98,4494.25 4961.2,4507.67 4957.67,4511.2 4944.25,4506.98
  pour cut-out net I2C1_SCL: 4973.33,4537.19 4970.85,4524.39 4975.48,4521.94 4989.25,4528.77
  pour cut-out net UART2_TX: 4452.06,5139.01 4439.59,5135 4439.59,5125 4452.06,5120.99
  pour cut-out net KEY: 4482.06,4894.01 4469.59,4887.5 4469.59,4882.5 4482.06,4875.99
  pour cut-out net KEY: 3732.94,5170.99 3745.41,5177.5 3745.41,5182.5 3732.94,5189.01
  pour cut-out net RST: 5079.01,5097.94 5072.5,5110.41 5067.5,5110.41 5060.99,5097.94
  pour cut-out net RST: 5167.06,5269.01 5154.59,5262.5 5154.59,5257.5 5167.06,5250.99
  pour cut-out net UART3_RX: 4788.3,4642.06 4794.81,4629.59 4799.81,4629.59 4806.31,4642.06
  pour cut-out net UART3_TX: 4804.25,4673.02 4817.67,4668.8 4821.2,4672.33 4816.98,4685.75
  pour cut-out net UART3_TX: 5285.75,4401.98 5272.33,4406.2 5268.8,4402.67 5273.02,4389.25
  pour cut-out net UART3_RX: 5187.06,4409.01 5174.59,4402.5 5174.59,4397.5 5187.06,4390.99
  pour cut-out net DP: 5639.01,4302.94 5635,4315.41 5625,4315.41 5620.99,4302.94
  pour cut-out net DN: 5619.01,4222.94 5615,4235.41 5605,4235.41 5600.99,4222.94
  pour cut-out net DN: 5614.01,4277.94 5610,4290.41 5600,4290.41 5595.99,4277.94
  pour cut-out net DN: 5600.12,4259.03 5605,4247.55 5615,4252.13 5616.5,4266.53
  pour cut-out net DP: 5567.19,4256.67 5555.61,4261.46 5550.72,4252.21 5558.77,4240.75
  pour cut-out net DN: 5564.25,4378.02 5575.9,4372.03 5582.97,4379.1 5576.98,4390.75
  pour cut-out net DP: 5490.99,4332.06 5495,4319.59 5505,4319.59 5509.01,4332.06
  pour cut-out net DP: 5511.98,4339.25 5517.97,4350.9 5510.9,4357.97 5499.25,4351.98
  pour cut-out net 3V3: 4247.94,4935.99 4260.41,4940 4260.41,4950 4247.94,4954.01
  pour cut-out net KEY: 4456.61,4894.01 4444.14,4887.5 4444.14,4882.5 4456.61,4875.99
  pour cut-out net KEY: 4472.5,4875.99 4484.97,4882.5 4484.97,4887.5 4472.5,4894.01

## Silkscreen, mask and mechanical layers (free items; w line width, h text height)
Top Overlay:
  text "JLCJLCJLCJLC" at 5783.9,4574.8 h32.45 r90
  text "疆来计划" at 3980.49,4430.08 h135.94
  text "JLJH22" at 3970,4325 h95
Bottom Overlay:
  lines w2: 5218.4,4090 5375,4090 5375,4250 5218.4,4250 5218.4,4090
  text "220731" at 5440.78,3956.72 h90.62
  text "V2" at 3733.65,3781.1 h32.45
Mechanical 1:
  lines w10: 3623.9,3732.91 5986.1,3732.91 5986.1,5347.09 3623.9,5347.09 3623.9,3732.91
